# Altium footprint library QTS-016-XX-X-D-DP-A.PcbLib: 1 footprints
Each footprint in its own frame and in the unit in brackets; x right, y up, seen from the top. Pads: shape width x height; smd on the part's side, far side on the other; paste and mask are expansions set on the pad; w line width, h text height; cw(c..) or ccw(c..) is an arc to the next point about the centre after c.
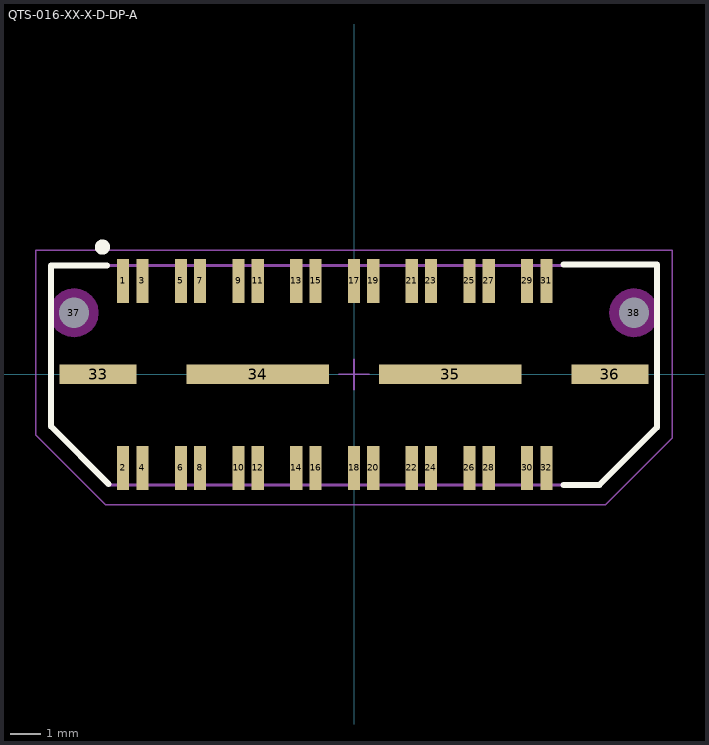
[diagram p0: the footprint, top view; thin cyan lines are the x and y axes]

## QTS-016-XX-X-D-DP-A [mm] "0.635mm pitch, 32 pin, high speed terminal; differential"
height 4.27
pads (38):
  rect 0.4x1.45 smd mask+0: 1(-7.62,3.086) 2(-7.62,-3.086) 3(-6.985,3.086) 4(-6.985,-3.086) 5(-5.715,3.086) 6(-5.715,-3.086) 7(-5.08,3.086) 8(-5.08,-3.086) 9(-3.81,3.086) 10(-3.81,-3.086) 11(-3.175,3.086) 12(-3.175,-3.086) 13(-1.905,3.086) 14(-1.905,-3.086) 15(-1.27,3.086) 16(-1.27,-3.086) 17(0,3.086) 18(0,-3.086) 19(0.635,3.086) 20(0.635,-3.086) 21(1.905,3.086) 22(1.905,-3.086) 23(2.54,3.086) 24(2.54,-3.086) 25(3.81,3.086) 26(3.81,-3.086) 27(4.445,3.086) 28(4.445,-3.086) 29(5.715,3.086) 30(5.715,-3.086) 31(6.35,3.086) 32(6.35,-3.086)
  rect 2.55x0.65 smd mask+0: 33(-8.445,0) 36(8.445,0)
  rect 4.7x0.65 smd mask+0: 34(-3.175,0) 35(3.175,0)
  round 0.5 hole 1 unplated mask+0: 37(-9.24,2.032) 38(9.238,2.032)
Top Overlay:
  circle w0.25: c-8.3,4.2 r0.125
  lines w0.2: -8.16,3.6 -10,3.6 -10,-1.716 -8.096,-3.619 ; 6.906,-3.65 8.1,-3.65 10,-1.75 10,3.619 6.906,3.619
Keep-Out Layer:
  pour cut-out: -8.433,2.032 -8.461,2.241 -8.541,2.435 -8.669,2.603 -8.837,2.731 -9.031,2.811 -9.24,2.839 -9.449,2.811 -9.643,2.731 -9.811,2.603 -9.939,2.435 -10.019,2.241 -10.047,2.032 -10.019,1.823 -9.939,1.629 -9.811,1.461 -9.643,1.333 -9.449,1.253 -9.24,1.225 -9.031,1.253 -8.837,1.333 -8.669,1.461 -8.541,1.629 -8.461,1.823
  pour cut-out: 10.045,2.032 10.017,2.241 9.937,2.435 9.809,2.603 9.641,2.731 9.447,2.811 9.238,2.839 9.029,2.811 8.835,2.731 8.667,2.603 8.539,2.435 8.459,2.241 8.431,2.032 8.459,1.823 8.539,1.629 8.667,1.461 8.835,1.333 9.029,1.253 9.238,1.225 9.447,1.253 9.641,1.333 9.809,1.461 9.937,1.629 10.017,1.823
Mechanical 12:
  lines w0.001: -10,-1.716 -10,3.6 10,3.6 10,-1.75 8.096,-3.65 -8.05,-3.65 -10,-1.716
Mechanical 13:
  lines w0.1: -10,-1.716 -10,3.6 10,3.6 10,-1.75 8.096,-3.65 -8.05,-3.65 -10,-1.716
  text ".Designator" at 0,-0.127 h1.52
Mechanical 15:
  lines w0.05: -0.5,0 0.5,0 ; 0,-0.5 0,0.5 ; -10.5,-2 -10.5,4.1 10.5,4.1 10.5,-2.1 8.3,-4.3 -8.2,-4.3 -10.5,-2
